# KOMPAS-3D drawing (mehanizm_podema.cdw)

Referenced files in C:\Milord\: механизм подъема.cdw
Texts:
  СДМ1-12.00.000 СБ
  Механизм подъёма сборочный чертеж
  Zver
  Microsoft
  Текст на чертеже
  Размерные надписи
  Шероховатость
  Линия-выноска #1
  Линия-выноска #2
  Линия-выноска #3
  Отклонения формы и база
  Заголовок таблицы
  Ячейка таблицы
  Стрелка вида
  Обозначение изменения
  Фигурная скобка
  Номер узла
  Марка координационной оси
  VRCB
  Выносная надпись
  Обозначение узла
  Марка/позиционное обозначение с линией-выноской
  Марка/позиционное обозначение на линии
  Марка/позиционное обозначение без линии-выноски
  Ошибки наложения элементов
  Техническая характеристика
  Электродвигатель:
  Редуктор:
  мощность, кВт
  1.   Размеры для справок
  2.  Неуказанные предельные отклонения: H14, h14 IT14 2
  3. Редуктор заполнить маслом М-8А (ГОСТ 10541-78).
  4. Тормоз  заполнить маслом АМГ (ГОСТ 6704-53).
  Технические требования
  ACAD_ISO10W100_RGB_0_0_0_SC_1_THICK_0.15
  ACAD_ISO04W100_RGB_0_0_0_SC_1_THICK_0.15
  ACAD_ISO10W100_RGB_0_0_0_SC_0.5_THICK_0.15
  ACAD_ISO04W100_RGB_0_0_0_SC_1_THICK_0.3
  ACAD_ISO04W100_RGB_51_51_51_SC_1_THICK_0.15
  ACAD_ISO10W100_RGB_51_51_51_SC_1_THICK_0.15
  ACAD_ISO10W100_RGB_51_51_51_SC_1_THICK_0.25
  ACAD_ISO10W100_RGB_51_51_51_SC_1_THICK_0.3
  POLYLINE_STYLE_0.18_RGB_51_51_51
  CONTINUOUS_RGB_0_0_0_THICK_0.18
  Ошибки
  POLYLINE_STYLE_0.34_RGB_0_0_0
  $$$$$$$$$_RGB_0_0_0_SC_1_THICK_0.18
  POLYLINE_STYLE_0.59_RGB_0_0_0
  POLYLINE_STYLE_0.39_RGB_0_0_0
  POLYLINE_STYLE_0.45_RGB_0_0_0
  POLYLINE_STYLE_0.18_RGB_0_0_0
  СONTINUOUS_RGB_0_0_0_THICK_0.18
  K5LT_AXLED_RGB_0_0_0_SC_1_THICK_0.13
  K5LT_AXLED_RGB_0_0_0_SC_0.3_THICK_0
  K5LT_AXLED_RGB_0_0_0_SC_0.3_THICK_0.13
  K5LT_AXLED_RGB_0_0_0_SC_0.1_THICK_0.13
  K5LT_AXLED_RGB_0_0_0_SC_1_THICK_0.15
  CONT_RGB_0_0_0_SC_1_THICK_0.18
  Черчение черная
  Шайба 6 ГОСТ 10906-78
  Шайба
  .Ти9
  ГОСТ
  Шайба 6 Т ГОСТ 6402-70
  Шайба пружинная
  ANSI37
  СДМ1-12.00.000 СБ-
  Кузьмич
  Передня
  Механизм подъёма
  сборочный чертеж
Dimensions and other numbers on the sheet: 7; 330; 1345; 390; 924; 320; 500; 2030; 175; 68; 50; 1; 2; 3; 4; 5; 8; 12; 14; 6; 9; 13; 15; 10; 11; 16; 17; 136; 78; 65Г; 029; 70; 0,000827; 1:5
